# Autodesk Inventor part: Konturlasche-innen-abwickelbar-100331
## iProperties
Created: 2010-03
Part Number: Konturlasche-innen-abwickelbar-100331
Material: ---
Catalog Web Link: www.waltertecyard.com
Document SubType Name: Blech
Designer: R.Schröder
Engineer: Dr.-Ing. Roland Schröder
Flat Pattern Width: 2.86082 cm
Flat Pattern Length: 3.7951 cm
Flat Pattern Area: 10.8571 cm^2
Sheet Metal Rule: Standard_mm
Category: Zeichnung
Manager: Dr.-Ing. Roland Schröder
Company: Walter Tecyard GmbH & Co. KG
Author: R.Schröder
w: 0,5
r: 0,5
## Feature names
1. Grobblech1
2. Grobblech2
3. Biegung1
4. Ausklinkung1
5. Ausklinkung2
